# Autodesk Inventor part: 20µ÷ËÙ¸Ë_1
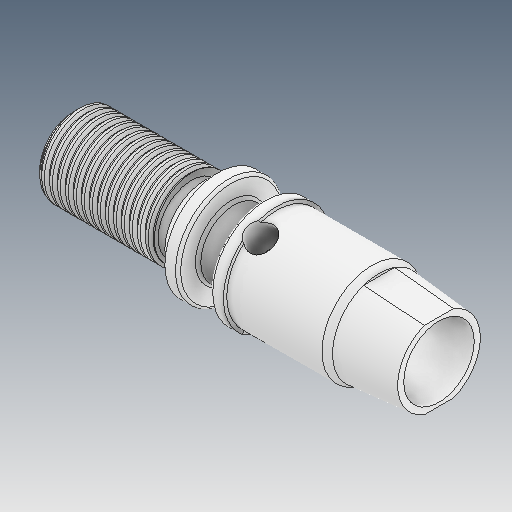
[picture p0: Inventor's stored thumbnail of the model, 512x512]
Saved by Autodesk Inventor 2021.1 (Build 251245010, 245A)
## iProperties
Created: 2021-05
Part Number: 20µ÷ËÙ¸Ë_1
Material: Ogólny
Document SubType Name: Modeling
Designer: user
Density: 1 g/cm^3
Appearance: Domyślna
Author: user
Revision Number: ÈÎºÎ
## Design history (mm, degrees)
feature "ÊäÈë1"
node "Bryła1"
